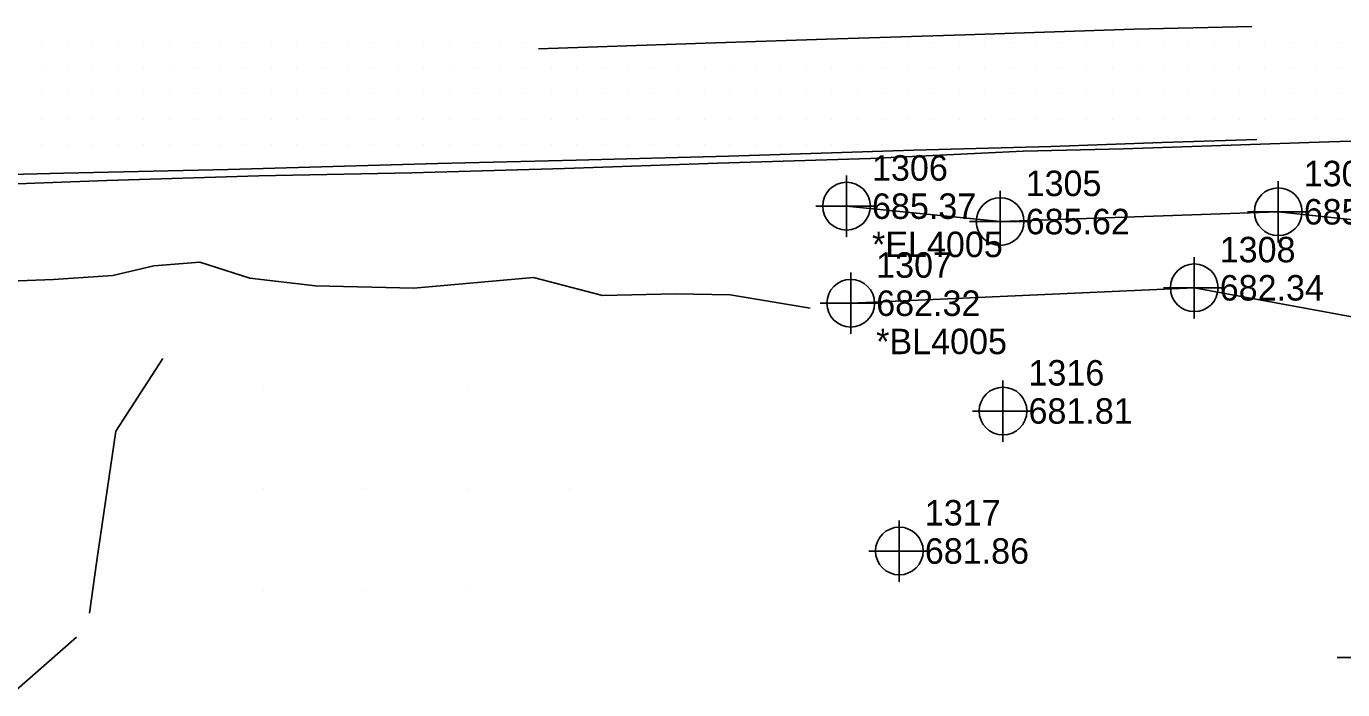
# Model space of a CAD drawing. Extents: x 1755643 to 1760494, y 736519 to 737621.
# Drawn here: x 1758922.2 to 1759051.4, y 736955.3 to 737020.4 of the extents above; entities that cross this region are included whole.
import ezdxf

# ---------------------------------------------------------------- set-up
doc = ezdxf.new("R2010")
doc.units = 0
for name, color, linetype in [('Exist Horizontal Alignment Curve and Spiral Data', 7, 'Continuous'), ('Exist Horizontal Alignment Direction Label', 7, 'Continuous'), ('Exist Railroads Standard Gauge', 7, 'Continuous'), ('Exist Roads EOT', 7, 'Continuous'), ('Old_Level_3', 7, 'Continuous'), ('Prop EOT Dash', 7, 'Continuous'), ('Prop Lane Lines', 7, 'Continuous'), ('Prop Paint Stripe', 7, 'Continuous'), ('Prop Paved Shoulder', 7, 'Continuous'), ('Scratch_Level_1', 7, 'Continuous'), ('Scratch_Level_2', 7, 'Continuous'), ('Scratch_Level_5', 7, 'Continuous'), ('Scratch_Level_9', 7, 'Continuous')]:
    doc.layers.add(name, color=color, linetype=linetype)

msp = doc.modelspace()

# ---------------------------------------------------------------- linework, layer by layer
at = {"layer": 'Exist Horizontal Alignment Curve and Spiral Data'}
for points in [[(1759018.05, 736985.62), (1759018.05, 736979.62), (1759018.05, 736982.62), (1759021.05, 736982.62), (1759015.05, 736982.62)], [(1759007.88, 736971.89), (1759007.88, 736965.89), (1759007.88, 736968.89), (1759010.88, 736968.89), (1759004.88, 736968.89)]]:
    msp.add_lwpolyline(points, dxfattribs=at)
for centre in [(1759018.05, 736982.62), (1759007.88, 736968.89)]:
    msp.add_circle(centre, 2.34, dxfattribs=at)
at = {"layer": 'Exist Railroads Standard Gauge'}
for points in [[(1758917.13, 736995.24), (1758924.92, 736995.52), (1758930.72, 736995.92), (1758934.76, 736996.88), (1758939.25, 736997.21), (1758944.17, 736995.65), (1758950.62, 736994.91), (1758960.26, 736994.69), (1758972, 736995.71), (1758978.75, 736993.96), (1758985.92, 736994.12), (1758991.28, 736994.03), (1758999.12, 736992.7)], [(1758928.42, 736962.8), (1758929.15, 736967.97), (1758931.03, 736980.64), (1758935.63, 736987.78)], [(1758900.9, 736883.3), (1758901.55, 736895.09), (1758902.46, 736915.93), (1758908.88, 736929.25), (1758914.62, 736938.9), (1758919.68, 736953.85), (1758927.16, 736960.45)]]:
    msp.add_lwpolyline(points, dxfattribs=at)
at = {"layer": 'Prop Lane Lines'}
for points in [[(1759002.7, 737005.72), (1759002.7, 736999.72), (1759002.7, 737002.72), (1759005.7, 737002.72), (1758999.7, 737002.72)], [(1759045.05, 737005.17), (1759045.05, 736999.17), (1759045.05, 737002.17), (1759048.05, 737002.17), (1759042.05, 737002.17)], [(1759017.77, 737004.21), (1759017.77, 736998.21), (1759017.77, 737001.21), (1759020.77, 737001.21), (1759014.77, 737001.21)], [(1759036.81, 736997.71), (1759036.81, 736991.71), (1759036.81, 736994.71), (1759039.81, 736994.71), (1759033.81, 736994.71)], [(1759003.11, 736996.2), (1759003.11, 736990.2), (1759003.11, 736993.2), (1759006.11, 736993.2), (1759000.11, 736993.2)], [(1759053.84, 736961.45), (1759053.84, 736955.45), (1759053.84, 736958.45), (1759056.84, 736958.45), (1759050.84, 736958.45)]]:
    msp.add_lwpolyline(points, dxfattribs=at)
for centre in [(1759002.7, 737002.72), (1759045.05, 737002.17), (1759017.77, 737001.21), (1759036.81, 736994.71), (1759003.11, 736993.2)]:
    msp.add_circle(centre, 2.34, dxfattribs=at)
at = {"layer": 'Prop Paint Stripe'}
for p, q in [((1758945.5, 736984.98), (1758945.5, 736984.98)), ((1758965.5, 736984.98), (1758965.5, 736984.98)), ((1758945.5, 736974.98), (1758945.5, 736974.98)), ((1758955.5, 736974.98), (1758955.5, 736974.98)), ((1758965.5, 736974.98), (1758965.5, 736974.98)), ((1758975.51, 736974.98), (1758975.51, 736974.98)), ((1758945.5, 736964.98), (1758945.5, 736964.98)), ((1758955.5, 736964.98), (1758955.5, 736964.98)), ((1758965.5, 736964.98), (1758965.5, 736964.98))]:
    msp.add_line(p, q, dxfattribs=at)
at = {"layer": 'Scratch_Level_1'}
msp.add_lwpolyline([(1759065.02, 737009.48), (1759050.02, 737009.03), (1759029.86, 737008.36), (1759020.04, 737008.1), (1759005.05, 737007.39), (1758990.06, 737006.95), (1758975.04, 737006.42), (1758960.05, 737006), (1758945.06, 737005.7), (1758930.12, 737005.23), (1758915.13, 737004.67), (1758900.15, 737004.23), (1758885.1, 737003.7), (1758867.07, 737003.45)], dxfattribs=at)
at = {"layer": 'Scratch_Level_2'}
for p, q in [((1758923.75, 737018.75), (1758923.75, 737018.75)), ((1758926.25, 737018.75), (1758926.25, 737018.75)), ((1758928.75, 737018.75), (1758928.75, 737018.75)), ((1758931.25, 737018.75), (1758931.25, 737018.75)), ((1758933.75, 737018.75), (1758933.75, 737018.75)), ((1758936.25, 737018.75), (1758936.25, 737018.75)), ((1758938.75, 737018.75), (1758938.75, 737018.75)), ((1758941.25, 737018.75), (1758941.25, 737018.75)), ((1758943.75, 737018.75), (1758943.75, 737018.75)), ((1758946.25, 737018.75), (1758946.25, 737018.75)), ((1758948.75, 737018.75), (1758948.75, 737018.75)), ((1758951.25, 737018.75), (1758951.25, 737018.75)), ((1758953.75, 737018.75), (1758953.75, 737018.75)), ((1758956.25, 737018.75), (1758956.25, 737018.75)), ((1758958.75, 737018.75), (1758958.75, 737018.75)), ((1758961.25, 737018.75), (1758961.25, 737018.75)), ((1758963.75, 737018.75), (1758963.75, 737018.75)), ((1758966.25, 737018.75), (1758966.25, 737018.75)), ((1758968.75, 737018.75), (1758968.75, 737018.75)), ((1758971.25, 737018.75), (1758971.25, 737018.75)), ((1758973.75, 737018.75), (1758973.75, 737018.75)), ((1759006.25, 737018.75), (1759006.25, 737018.75)), ((1759008.75, 737018.75), (1759008.75, 737018.75)), ((1759011.25, 737018.75), (1759011.25, 737018.75)), ((1759013.75, 737018.75), (1759013.75, 737018.75)), ((1759016.25, 737018.75), (1759016.25, 737018.75)), ((1759018.75, 737018.75), (1759018.75, 737018.75)), ((1759021.25, 737018.75), (1759021.25, 737018.75)), ((1759023.75, 737018.75), (1759023.75, 737018.75)), ((1759026.25, 737018.75), (1759026.25, 737018.75)), ((1759028.75, 737018.75), (1759028.75, 737018.75)), ((1759031.25, 737018.75), (1759031.25, 737018.75)), ((1759033.75, 737018.75), (1759033.75, 737018.75)), ((1759036.25, 737018.75), (1759036.25, 737018.75)), ((1759038.75, 737018.75), (1759038.75, 737018.75)), ((1759041.25, 737018.75), (1759041.25, 737018.75)), ((1759043.75, 737018.75), (1759043.75, 737018.75)), ((1759046.25, 737018.75), (1759046.25, 737018.75)), ((1759048.75, 737018.75), (1759048.75, 737018.75)), ((1759051.25, 737018.75), (1759051.25, 737018.75)), ((1758923.75, 737016.25), (1758923.75, 737016.25)), ((1758926.25, 737016.25), (1758926.25, 737016.25)), ((1758928.75, 737016.25), (1758928.75, 737016.25)), ((1758931.25, 737016.25), (1758931.25, 737016.25)), ((1758933.75, 737016.25), (1758933.75, 737016.25)), ((1758936.25, 737016.25), (1758936.25, 737016.25)), ((1758938.75, 737016.25), (1758938.75, 737016.25)), ((1758941.25, 737016.25), (1758941.25, 737016.25)), ((1758943.75, 737016.25), (1758943.75, 737016.25)), ((1758946.25, 737016.25), (1758946.25, 737016.25)), ((1758948.75, 737016.25), (1758948.75, 737016.25)), ((1758951.25, 737016.25), (1758951.25, 737016.25)), ((1758953.75, 737016.25), (1758953.75, 737016.25)), ((1758956.25, 737016.25), (1758956.25, 737016.25)), ((1758958.75, 737016.25), (1758958.75, 737016.25)), ((1758961.25, 737016.25), (1758961.25, 737016.25)), ((1758963.75, 737016.25), (1758963.75, 737016.25)), ((1758966.25, 737016.25), (1758966.25, 737016.25)), ((1758968.75, 737016.25), (1758968.75, 737016.25)), ((1758971.25, 737016.25), (1758971.25, 737016.25)), ((1758973.75, 737016.25), (1758973.75, 737016.25)), ((1758976.25, 737016.25), (1758976.25, 737016.25)), ((1758978.75, 737016.25), (1758978.75, 737016.25)), ((1758981.25, 737016.25), (1758981.25, 737016.25)), ((1758983.75, 737016.25), (1758983.75, 737016.25)), ((1758986.25, 737016.25), (1758986.25, 737016.25)), ((1758988.75, 737016.25), (1758988.75, 737016.25)), ((1758991.25, 737016.25), (1758991.25, 737016.25)), ((1758993.75, 737016.25), (1758993.75, 737016.25)), ((1758996.25, 737016.25), (1758996.25, 737016.25)), ((1758998.75, 737016.25), (1758998.75, 737016.25)), ((1759001.25, 737016.25), (1759001.25, 737016.25)), ((1759003.75, 737016.25), (1759003.75, 737016.25)), ((1759006.25, 737016.25), (1759006.25, 737016.25)), ((1759008.75, 737016.25), (1759008.75, 737016.25)), ((1759011.25, 737016.25), (1759011.25, 737016.25)), ((1759013.75, 737016.25), (1759013.75, 737016.25)), ((1759016.25, 737016.25), (1759016.25, 737016.25)), ((1759018.75, 737016.25), (1759018.75, 737016.25)), ((1759021.25, 737016.25), (1759021.25, 737016.25)), ((1759023.75, 737016.25), (1759023.75, 737016.25)), ((1759026.25, 737016.25), (1759026.25, 737016.25)), ((1759028.75, 737016.25), (1759028.75, 737016.25)), ((1759031.25, 737016.25), (1759031.25, 737016.25)), ((1759033.75, 737016.25), (1759033.75, 737016.25)), ((1759036.25, 737016.25), (1759036.25, 737016.25)), ((1759038.75, 737016.25), (1759038.75, 737016.25)), ((1759041.25, 737016.25), (1759041.25, 737016.25)), ((1759043.75, 737016.25), (1759043.75, 737016.25)), ((1759046.25, 737016.25), (1759046.25, 737016.25)), ((1759048.75, 737016.25), (1759048.75, 737016.25)), ((1759051.25, 737016.25), (1759051.25, 737016.25)), ((1758923.75, 737013.75), (1758923.75, 737013.75)), ((1758926.25, 737013.75), (1758926.25, 737013.75)), ((1758928.75, 737013.75), (1758928.75, 737013.75)), ((1758931.25, 737013.75), (1758931.25, 737013.75)), ((1758933.75, 737013.75), (1758933.75, 737013.75)), ((1758936.25, 737013.75), (1758936.25, 737013.75)), ((1758938.75, 737013.75), (1758938.75, 737013.75)), ((1758941.25, 737013.75), (1758941.25, 737013.75)), ((1758943.75, 737013.75), (1758943.75, 737013.75)), ((1758946.25, 737013.75), (1758946.25, 737013.75)), ((1758948.75, 737013.75), (1758948.75, 737013.75)), ((1758951.25, 737013.75), (1758951.25, 737013.75)), ((1758953.75, 737013.75), (1758953.75, 737013.75)), ((1758956.25, 737013.75), (1758956.25, 737013.75)), ((1758958.75, 737013.75), (1758958.75, 737013.75)), ((1758961.25, 737013.75), (1758961.25, 737013.75)), ((1758963.75, 737013.75), (1758963.75, 737013.75)), ((1758966.25, 737013.75), (1758966.25, 737013.75)), ((1758968.75, 737013.75), (1758968.75, 737013.75)), ((1758971.25, 737013.75), (1758971.25, 737013.75)), ((1758973.75, 737013.75), (1758973.75, 737013.75)), ((1758976.25, 737013.75), (1758976.25, 737013.75)), ((1758978.75, 737013.75), (1758978.75, 737013.75)), ((1758981.25, 737013.75), (1758981.25, 737013.75)), ((1758983.75, 737013.75), (1758983.75, 737013.75)), ((1758986.25, 737013.75), (1758986.25, 737013.75)), ((1758988.75, 737013.75), (1758988.75, 737013.75)), ((1758991.25, 737013.75), (1758991.25, 737013.75)), ((1758993.75, 737013.75), (1758993.75, 737013.75)), ((1758996.25, 737013.75), (1758996.25, 737013.75)), ((1758998.75, 737013.75), (1758998.75, 737013.75)), ((1759001.25, 737013.75), (1759001.25, 737013.75)), ((1759003.75, 737013.75), (1759003.75, 737013.75)), ((1759006.25, 737013.75), (1759006.25, 737013.75)), ((1759008.75, 737013.75), (1759008.75, 737013.75)), ((1759011.25, 737013.75), (1759011.25, 737013.75)), ((1759013.75, 737013.75), (1759013.75, 737013.75)), ((1759016.25, 737013.75), (1759016.25, 737013.75)), ((1759018.75, 737013.75), (1759018.75, 737013.75)), ((1759021.25, 737013.75), (1759021.25, 737013.75)), ((1759023.75, 737013.75), (1759023.75, 737013.75)), ((1759026.25, 737013.75), (1759026.25, 737013.75)), ((1759028.75, 737013.75), (1759028.75, 737013.75)), ((1759031.25, 737013.75), (1759031.25, 737013.75)), ((1759033.75, 737013.75), (1759033.75, 737013.75)), ((1759036.25, 737013.75), (1759036.25, 737013.75)), ((1759038.75, 737013.75), (1759038.75, 737013.75)), ((1759041.25, 737013.75), (1759041.25, 737013.75)), ((1759043.75, 737013.75), (1759043.75, 737013.75)), ((1759046.25, 737013.75), (1759046.25, 737013.75)), ((1759048.75, 737013.75), (1759048.75, 737013.75)), ((1759051.25, 737013.75), (1759051.25, 737013.75)), ((1758923.75, 737011.25), (1758923.75, 737011.25)), ((1758926.25, 737011.25), (1758926.25, 737011.25)), ((1758928.75, 737011.25), (1758928.75, 737011.25)), ((1758931.25, 737011.25), (1758931.25, 737011.25)), ((1758933.75, 737011.25), (1758933.75, 737011.25)), ((1758936.25, 737011.25), (1758936.25, 737011.25)), ((1758938.75, 737011.25), (1758938.75, 737011.25)), ((1758941.25, 737011.25), (1758941.25, 737011.25)), ((1758943.75, 737011.25), (1758943.75, 737011.25)), ((1758946.25, 737011.25), (1758946.25, 737011.25)), ((1758948.75, 737011.25), (1758948.75, 737011.25)), ((1758951.25, 737011.25), (1758951.25, 737011.25)), ((1758953.75, 737011.25), (1758953.75, 737011.25)), ((1758956.25, 737011.25), (1758956.25, 737011.25)), ((1758958.75, 737011.25), (1758958.75, 737011.25)), ((1758961.25, 737011.25), (1758961.25, 737011.25)), ((1758963.75, 737011.25), (1758963.75, 737011.25)), ((1758966.25, 737011.25), (1758966.25, 737011.25)), ((1758968.75, 737011.25), (1758968.75, 737011.25)), ((1758971.25, 737011.25), (1758971.25, 737011.25)), ((1758973.75, 737011.25), (1758973.75, 737011.25)), ((1758976.25, 737011.25), (1758976.25, 737011.25)), ((1758978.75, 737011.25), (1758978.75, 737011.25)), ((1758981.25, 737011.25), (1758981.25, 737011.25)), ((1758983.75, 737011.25), (1758983.75, 737011.25)), ((1758986.25, 737011.25), (1758986.25, 737011.25)), ((1758988.75, 737011.25), (1758988.75, 737011.25)), ((1758991.25, 737011.25), (1758991.25, 737011.25)), ((1758993.75, 737011.25), (1758993.75, 737011.25)), ((1758996.25, 737011.25), (1758996.25, 737011.25)), ((1758998.75, 737011.25), (1758998.75, 737011.25)), ((1759001.25, 737011.25), (1759001.25, 737011.25)), ((1759003.75, 737011.25), (1759003.75, 737011.25)), ((1759006.25, 737011.25), (1759006.25, 737011.25)), ((1759008.75, 737011.25), (1759008.75, 737011.25)), ((1759011.25, 737011.25), (1759011.25, 737011.25)), ((1759013.75, 737011.25), (1759013.75, 737011.25)), ((1759016.25, 737011.25), (1759016.25, 737011.25)), ((1759018.75, 737011.25), (1759018.75, 737011.25)), ((1759021.25, 737011.25), (1759021.25, 737011.25)), ((1759023.75, 737011.25), (1759023.75, 737011.25)), ((1759026.25, 737011.25), (1759026.25, 737011.25)), ((1759028.75, 737011.25), (1759028.75, 737011.25)), ((1759031.25, 737011.25), (1759031.25, 737011.25)), ((1759033.75, 737011.25), (1759033.75, 737011.25)), ((1759036.25, 737011.25), (1759036.25, 737011.25)), ((1759038.75, 737011.25), (1759038.75, 737011.25)), ((1759041.25, 737011.25), (1759041.25, 737011.25)), ((1759043.75, 737011.25), (1759043.75, 737011.25)), ((1759046.25, 737011.25), (1759046.25, 737011.25)), ((1759048.75, 737011.25), (1759048.75, 737011.25)), ((1759051.25, 737011.25), (1759051.25, 737011.25)), ((1758923.75, 737008.75), (1758923.75, 737008.75)), ((1758926.25, 737008.75), (1758926.25, 737008.75)), ((1758928.75, 737008.75), (1758928.75, 737008.75)), ((1758931.25, 737008.75), (1758931.25, 737008.75)), ((1758933.75, 737008.75), (1758933.75, 737008.75)), ((1758936.25, 737008.75), (1758936.25, 737008.75)), ((1758938.75, 737008.75), (1758938.75, 737008.75)), ((1758941.25, 737008.75), (1758941.25, 737008.75)), ((1758943.75, 737008.75), (1758943.75, 737008.75)), ((1758946.25, 737008.75), (1758946.25, 737008.75)), ((1758948.75, 737008.75), (1758948.75, 737008.75)), ((1758951.25, 737008.75), (1758951.25, 737008.75)), ((1758953.75, 737008.75), (1758953.75, 737008.75)), ((1758956.25, 737008.75), (1758956.25, 737008.75)), ((1758958.75, 737008.75), (1758958.75, 737008.75)), ((1758961.25, 737008.75), (1758961.25, 737008.75)), ((1758963.75, 737008.75), (1758963.75, 737008.75)), ((1758966.25, 737008.75), (1758966.25, 737008.75)), ((1758968.75, 737008.75), (1758968.75, 737008.75)), ((1758971.25, 737008.75), (1758971.25, 737008.75)), ((1758973.75, 737008.75), (1758973.75, 737008.75)), ((1758976.25, 737008.75), (1758976.25, 737008.75)), ((1758978.75, 737008.75), (1758978.75, 737008.75)), ((1758981.25, 737008.75), (1758981.25, 737008.75)), ((1758983.75, 737008.75), (1758983.75, 737008.75)), ((1758986.25, 737008.75), (1758986.25, 737008.75)), ((1758988.75, 737008.75), (1758988.75, 737008.75)), ((1758991.25, 737008.75), (1758991.25, 737008.75)), ((1758993.75, 737008.75), (1758993.75, 737008.75)), ((1758996.25, 737008.75), (1758996.25, 737008.75)), ((1758998.75, 737008.75), (1758998.75, 737008.75)), ((1759001.25, 737008.75), (1759001.25, 737008.75)), ((1759003.75, 737008.75), (1759003.75, 737008.75)), ((1759006.25, 737008.75), (1759006.25, 737008.75)), ((1759008.75, 737008.75), (1759008.75, 737008.75)), ((1759011.25, 737008.75), (1759011.25, 737008.75))]:
    msp.add_line(p, q, dxfattribs=at)
at = {"layer": 'Scratch_Level_5'}
for points in [[(1758972.48, 737018.17), (1758987.88, 737018.67), (1759000.73, 737019.1), (1759014.29, 737019.53), (1759030.91, 737020.09), (1759042.45, 737020.36)], [(1759042.94, 737009.26), (1759033.66, 737008.96), (1759022.73, 737008.57), (1759009.29, 737008.2), (1758991.12, 737007.62), (1758976.19, 737007.23), (1758962.61, 737006.89), (1758942.03, 737006.32), (1758925.9, 737005.96), (1758908.83, 737005.52)]]:
    msp.add_lwpolyline(points, dxfattribs=at)
at = {"layer": 'Scratch_Level_9'}
for points in [[(1759108.25, 736984.06), (1759108.2, 736990.92), (1759102.65, 736999.08), (1759069.97, 736999.5), (1759045.05, 737002.17), (1759017.77, 737001.21), (1759002.7, 737002.72)], [(1759003.11, 736993.2), (1759036.81, 736994.71), (1759065.3, 736989.46), (1759078.2, 736989.57), (1759080.92, 736976.07), (1759076.94, 736972)]]:
    msp.add_lwpolyline(points, dxfattribs=at)

# ---------------------------------------------------------------- texts
at = {"layer": 'Exist Horizontal Alignment Direction Label'}
for s, p in [('*EL4005', (1759005.2, 736997.72)), ('*BL4005', (1759005.61, 736988.2))]:
    msp.add_text(s, height=2.5, dxfattribs=at).set_placement(p)
at = {"layer": 'Exist Roads EOT'}
for s, p in [('1316', (1759020.55, 736985.12)), ('1317', (1759010.38, 736971.39))]:
    msp.add_text(s, height=2.5, dxfattribs=at).set_placement(p)
at = {"layer": 'Old_Level_3'}
for s, p in [('685.37', (1759005.2, 737001.47)), ('685.70', (1759047.55, 737000.92)), ('685.62', (1759020.27, 736999.96)), ('682.34', (1759039.31, 736993.46)), ('682.32', (1759005.61, 736991.95))]:
    msp.add_text(s, height=2.5, dxfattribs=at).set_placement(p)
at = {"layer": 'Prop EOT Dash'}
for s, p in [('1306', (1759005.2, 737005.22)), ('1304', (1759047.55, 737004.67)), ('1305', (1759020.27, 737003.71)), ('1308', (1759039.31, 736997.21)), ('1307', (1759005.61, 736995.7))]:
    msp.add_text(s, height=2.5, dxfattribs=at).set_placement(p)
at = {"layer": 'Prop Paved Shoulder'}
for s, p in [('681.81', (1759020.55, 736981.38)), ('681.86', (1759010.38, 736967.64))]:
    msp.add_text(s, height=2.5, dxfattribs=at).set_placement(p)

doc.saveas('drawing.dxf')
